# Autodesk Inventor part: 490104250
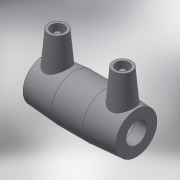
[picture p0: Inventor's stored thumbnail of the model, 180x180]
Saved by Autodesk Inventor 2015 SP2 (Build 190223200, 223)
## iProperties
Created: 2017-06
Part Number: 490104250
Material: Generic
Description: PLASSON COUPLER 250-250
Document SubType Name: Modeling
Designer: KIM
Mass: 55.0731 g
Surface Area: 148.067 cm^2
Volume: 55.0731 cm^3
Density: 1 g/cm^3
Appearance: Default
Author: KIM
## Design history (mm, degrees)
derived "490104.ipt"
feature "Solid1::490104.ipt"
tag "TaggingFeature1"
body "Solid1"
other parameters: "d0" = 251, "d2" = 311, "d3" = 123, "d4" = 83.66667, "d5" = 279.9, "d6" = 237.5, "d8" = 168 deg, "d10" = 49.2, "d11" = 16.4, "d13" = 251, "d14" = 17.6296, "d15" = 123, "d16" = 123, "d17" = 237.5, "d19" = 3.52592, "d20" = 168 deg, "d22" = 292.34, "d23" = 311, "d24" = 283.5698, "d25" = 135 deg, "d26" = 125.5, "d27" = 135 deg, "d29" = 156, "d30" = 14, "d31" = 87.85, "d34" = 5 deg, "d35" = 15, "d39" = 5 deg, "d41" = 4, "d42" = 14, "d43" = 0, "d45" = 4, "d46" = 14, "d47" = 0, "d48" = 3, "d49" = 0, "d50" = 3, "d51" = 0, "d52" = 35.67, "d53" = 8.9175, "L_" = 251, "L_1" = 123, "D_" = 311, "A_" = 156, "d_2" = 12
